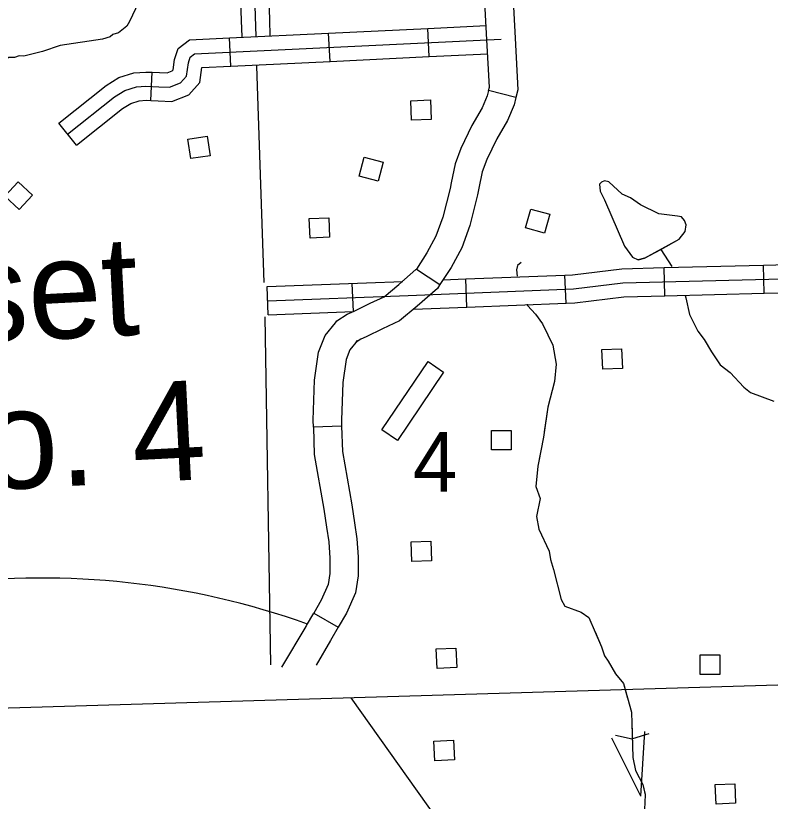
# Model space of a CAD drawing. Extents: x 1671357 to 13005564, y 567358 to 14261451.
# Drawn here: x 12758301.586 to 12758302.925, y 14259944.134 to 14259945.527 of the extents above; entities that cross this region are included whole.
import ezdxf

# ---------------------------------------------------------------- set-up
doc = ezdxf.new("R2010")
doc.units = 0
for name, color, linetype in [('31', 7, 'Continuous'), ('32', 7, 'Continuous'), ('35', 7, 'Continuous'), ('5', 7, 'Continuous'), ('56', 7, 'Continuous'), ('63', 7, 'Continuous'), ('Default', 7, 'Continuous')]:
    doc.layers.add(name, color=color, linetype=linetype)

msp = doc.modelspace()

# ---------------------------------------------------------------- linework, layer by layer
at = {"layer": '31'}
for p, q in [((12758302.4737, 14259945.3818), (12758302.4252, 14259945.3944)), ((12758302.2971, 14259945.0776), (12758302.3389, 14259945.0502)), ((12758302.1645, 14259944.7991), (12758302.1145, 14259944.7975)), ((12758302.1151, 14259944.4675), (12758302.1585, 14259944.4425)), ((12758302.1585, 14259944.4425), (12758302.1585, 14259944.4425))]:
    msp.add_line(p, q, dxfattribs=at)
for points in [[(12758301.9805, 14259945.6949), (12758301.9864, 14259945.5187)], [(12758302.0305, 14259945.6966), (12758302.0364, 14259945.5204)], [(12758302.4252, 14259945.3944), (12758302.4268, 14259945.4005), (12758302.4223, 14259945.4843), (12758302.4181, 14259945.5625)], [(12758302.4681, 14259945.5651), (12758302.4723, 14259945.487), (12758302.4772, 14259945.3955), (12758302.4737, 14259945.3818)], [(12758302.0364, 14259945.5204), (12758302.0374, 14259945.491)], [(12758301.9864, 14259945.5187), (12758301.9874, 14259945.4893)], [(12758302.4252, 14259945.3944), (12758302.4228, 14259945.385), (12758302.4138, 14259945.3636), (12758302.3955, 14259945.3322), (12758302.3758, 14259945.2916), (12758302.3657, 14259945.2641), (12758302.359, 14259945.2308)], [(12758302.4737, 14259945.3818), (12758302.4704, 14259945.369), (12758302.4587, 14259945.3412), (12758302.4397, 14259945.3087), (12758302.422, 14259945.272), (12758302.4141, 14259945.2504), (12758302.4081, 14259945.2209)], [(12758302.359, 14259945.2308), (12758302.3569, 14259945.2206), (12758302.3439, 14259945.1698), (12758302.3318, 14259945.1359), (12758302.3159, 14259945.1063), (12758302.2971, 14259945.0776)], [(12758302.4081, 14259945.2209), (12758302.4058, 14259945.2094), (12758302.3919, 14259945.1552), (12758302.3777, 14259945.1155), (12758302.359, 14259945.0807), (12758302.3389, 14259945.0502)], [(12758302.1535, 14259944.9824), (12758302.1562, 14259944.9857), (12758302.1745, 14259944.9975), (12758302.1867, 14259945.0029), (12758302.2153, 14259945.0172), (12758302.2401, 14259945.0285), (12758302.2661, 14259945.0502), (12758302.2964, 14259945.0767), (12758302.2971, 14259945.0776)], [(12758302.3389, 14259945.0502), (12758302.3345, 14259945.0434), (12758302.2986, 14259945.0121), (12758302.2671, 14259944.9858), (12758302.2369, 14259944.972), (12758302.208, 14259944.9576), (12758302.1985, 14259944.9534), (12758302.1902, 14259944.948), (12758302.1926, 14259944.951)], [(12758302.1145, 14259944.7975), (12758302.1141, 14259944.8099), (12758302.1166, 14259944.8809), (12758302.1236, 14259944.9304), (12758302.1355, 14259944.9598), (12758302.1535, 14259944.9824)], [(12758302.1926, 14259944.951), (12758302.1792, 14259944.9343), (12758302.1723, 14259944.9173), (12758302.1665, 14259944.8765), (12758302.1642, 14259944.8098), (12758302.1645, 14259944.7991)], [(12758302.1145, 14259944.7975), (12758302.116, 14259944.7487), (12758302.133, 14259944.6518), (12758302.1377, 14259944.6201)], [(12758302.1645, 14259944.7991), (12758302.1659, 14259944.7539), (12758302.1824, 14259944.6598), (12758302.1873, 14259944.6275)], [(12758302.1873, 14259944.6275), (12758302.1915, 14259944.5993), (12758302.1939, 14259944.5671), (12758302.1939, 14259944.5336), (12758302.1891, 14259944.5038), (12758302.1729, 14259944.4675), (12758302.1585, 14259944.4425)], [(12758302.1377, 14259944.6201), (12758302.1417, 14259944.5937), (12758302.1438, 14259944.5652), (12758302.1438, 14259944.5377), (12758302.1407, 14259944.5182), (12758302.1282, 14259944.4903), (12758302.1151, 14259944.4675)], [(12758302.1023, 14259944.4453), (12758302.1151, 14259944.4675)], [(12758302.0587, 14259944.3715), (12758302.1016, 14259944.4441), (12758302.1023, 14259944.4453)], [(12758302.1585, 14259944.4425), (12758302.1448, 14259944.4188), (12758302.1191, 14259944.3752)]]:
    msp.add_lwpolyline(points, dxfattribs=at)
at = {"layer": '32'}
for p, q in [((12758302.1439, 14259945.4461), (12758302.1415, 14259945.4961)), ((12758302.32, 14259945.4545), (12758302.3176, 14259945.5045)), ((12758301.9678, 14259945.4377), (12758301.9654, 14259945.4877)), ((12758301.826, 14259945.3766), (12758301.8283, 14259945.4267)), ((12758301.694, 14259945.2972), (12758301.6628, 14259945.3363)), ((12758302.7379, 14259945.0303), (12758302.7367, 14259945.0803)), ((12758302.9141, 14259945.0347), (12758302.9129, 14259945.0847)), ((12758302.3865, 14259945.0102), (12758302.3846, 14259945.0602)), ((12758302.5627, 14259945.0171), (12758302.5607, 14259945.0671)), ((12758302.0342, 14259944.9965), (12758302.0323, 14259945.0465)), ((12758302.1854, 14259945.0023), (12758302.1834, 14259945.0524))]:
    msp.add_line(p, q, dxfattribs=at)
for points in [[(12758302.3176, 14259945.5045), (12758302.4209, 14259945.5094)], [(12758301.9654, 14259945.4877), (12758302.1415, 14259945.4961)], [(12758302.1415, 14259945.4961), (12758302.3176, 14259945.5045)], [(12758301.6784, 14259945.3167), (12758301.7614, 14259945.3829), (12758301.7799, 14259945.3945), (12758301.8004, 14259945.401), (12758301.8174, 14259945.4021), (12758301.8404, 14259945.4011), (12758301.8592, 14259945.4002), (12758301.8785, 14259945.4081), (12758301.8891, 14259945.4196), (12758301.8927, 14259945.4435), (12758301.896, 14259945.4537), (12758301.9037, 14259945.4597), (12758302.4473, 14259945.4856)], [(12758301.8283, 14259945.4267), (12758301.8416, 14259945.4261), (12758301.8549, 14259945.4255), (12758301.8639, 14259945.4291), (12758301.8655, 14259945.4309), (12758301.8683, 14259945.4492), (12758301.8745, 14259945.4687), (12758301.8946, 14259945.4844), (12758301.9654, 14259945.4877)], [(12758302.1439, 14259945.4461), (12758302.32, 14259945.4545)], [(12758302.32, 14259945.4545), (12758302.4236, 14259945.4594)], [(12758301.826, 14259945.3766), (12758301.8393, 14259945.3761), (12758301.8635, 14259945.3749), (12758301.8932, 14259945.387), (12758301.9127, 14259945.4083), (12758301.9168, 14259945.4353), (12758301.9678, 14259945.4377)], [(12758301.9678, 14259945.4377), (12758302.1439, 14259945.4461)], [(12758301.6628, 14259945.3363), (12758301.7469, 14259945.4034), (12758301.7694, 14259945.4174), (12758301.7957, 14259945.4258), (12758301.8171, 14259945.4272), (12758301.8283, 14259945.4267)], [(12758301.694, 14259945.2972), (12758301.7759, 14259945.3625), (12758301.7905, 14259945.3716), (12758301.8051, 14259945.3762), (12758301.8176, 14259945.377), (12758301.826, 14259945.3766)], [(12758302.9129, 14259945.0847), (12758303.0891, 14259945.0891)], [(12758302.0333, 14259945.0215), (12758302.2823, 14259945.0311), (12758302.576, 14259945.0427), (12758302.6634, 14259945.0534), (12758303.3459, 14259945.0705), (12758303.4823, 14259945.076)], [(12758302.5607, 14259945.0671), (12758302.574, 14259945.0677), (12758302.6616, 14259945.0784), (12758302.7367, 14259945.0803)], [(12758302.7367, 14259945.0803), (12758302.9129, 14259945.0847)], [(12758302.3441, 14259945.0586), (12758302.3846, 14259945.0602)], [(12758302.3846, 14259945.0602), (12758302.5607, 14259945.0671)], [(12758302.0323, 14259945.0465), (12758302.2084, 14259945.0533)], [(12758302.2084, 14259945.0533), (12758302.2733, 14259945.0559)], [(12758302.7379, 14259945.0303), (12758302.9141, 14259945.0347)], [(12758302.9141, 14259945.0347), (12758303.0904, 14259945.0391)], [(12758302.5627, 14259945.0171), (12758302.5781, 14259945.0177), (12758302.6653, 14259945.0284), (12758302.7379, 14259945.0303)], [(12758302.2921, 14259945.0065), (12758302.3865, 14259945.0102)], [(12758302.3865, 14259945.0102), (12758302.5627, 14259945.0171)], [(12758302.0342, 14259944.9965), (12758302.1857, 14259945.0024)]]:
    msp.add_lwpolyline(points, dxfattribs=at)
at = {"layer": '35'}
for p, q in [((12758302.6502, 14259944.2513), (12758302.6799, 14259944.2444)), ((12758302.7095, 14259944.2534), (12758302.6803, 14259944.2445)), ((12758302.695, 14259944.1431), (12758302.7023, 14259944.2574)), ((12758302.695, 14259944.1431), (12758302.6441, 14259944.2457))]:
    msp.add_line(p, q, dxfattribs=at)
for points in [[(12758301.982, 14259945.6645), (12758301.9654, 14259945.6434), (12758301.9512, 14259945.624), (12758301.9323, 14259945.6044), (12758301.9217, 14259945.6026), (12758301.9082, 14259945.5983), (12758301.8803, 14259945.5938), (12758301.8453, 14259945.5923), (12758301.8292, 14259945.5869), (12758301.822, 14259945.5823), (12758301.8144, 14259945.5726), (12758301.7884, 14259945.5168), (12758301.7834, 14259945.5086), (12758301.7689, 14259945.4966), (12758301.7587, 14259945.4938), (12758301.7539, 14259945.4895), (12758301.7403, 14259945.4856), (12758301.6653, 14259945.4744), (12758301.6337, 14259945.4636), (12758301.6007, 14259945.4555), (12758301.5923, 14259945.4558), (12758301.5841, 14259945.4528), (12758301.5741, 14259945.4527), (12758301.5633, 14259945.4462)], [(12758302.731, 14259945.1123), (12758302.7633, 14259945.1308), (12758302.7737, 14259945.1443), (12758302.7759, 14259945.1564), (12758302.7729, 14259945.164), (12758302.7676, 14259945.1702), (12758302.7606, 14259945.1715), (12758302.727, 14259945.1758), (12758302.6949, 14259945.1915), (12758302.6767, 14259945.2042), (12758302.6624, 14259945.2106), (12758302.6388, 14259945.2324), (12758302.631, 14259945.2344), (12758302.6254, 14259945.2318), (12758302.6219, 14259945.2283), (12758302.6234, 14259945.2156), (12758302.6308, 14259945.2005)], [(12758302.6308, 14259945.2005), (12758302.6666, 14259945.1186), (12758302.6805, 14259945.0991), (12758302.6907, 14259945.0942), (12758302.7016, 14259945.097), (12758302.731, 14259945.1123)], [(12758302.7016, 14259945.097), (12758302.7633, 14259945.1308), (12758302.7737, 14259945.1443)], [(12758302.731, 14259945.1123), (12758302.7505, 14259945.0822)], [(12758302.4832, 14259945.0893), (12758302.4764, 14259945.084), (12758302.4748, 14259945.0762), (12758302.4759, 14259945.065)], [(12758302.7016, 14259945.097), (12758302.6907, 14259945.0942)], [(12758302.7738, 14259945.0307), (12758302.7751, 14259945.0267), (12758302.7817, 14259944.9972), (12758302.7963, 14259944.9673), (12758302.8076, 14259944.953), (12758302.8206, 14259944.9308), (12758302.8359, 14259944.908), (12758302.8539, 14259944.894), (12758302.8783, 14259944.8682), (12758302.8898, 14259944.859), (12758302.9315, 14259944.8437)], [(12758302.4934, 14259945.0153), (12758302.4945, 14259945.0131), (12758302.5085, 14259944.9976), (12758302.5209, 14259944.9803), (12758302.5392, 14259944.9426), (12758302.545, 14259944.909), (12758302.5423, 14259944.8783), (12758302.5305, 14259944.8326), (12758302.5224, 14259944.7796), (12758302.5126, 14259944.7279), (12758302.5092, 14259944.6919), (12758302.5167, 14259944.6708), (12758302.5101, 14259944.639), (12758302.5144, 14259944.6164), (12758302.5324, 14259944.5773), (12758302.535, 14259944.5627), (12758302.5405, 14259944.5448), (12758302.5537, 14259944.4917), (12758302.5606, 14259944.48), (12758302.5894, 14259944.4695), (12758302.6029, 14259944.46), (12758302.6254, 14259944.408), (12758302.6308, 14259944.3915), (12758302.6372, 14259944.3823), (12758302.6505, 14259944.3598), (12758302.6646, 14259944.343), (12758302.6785, 14259944.2919), (12758302.6812, 14259944.2116), (12758302.6859, 14259944.1884), (12758302.699, 14259944.1638)], [(12758302.4934, 14259945.0153), (12758302.4945, 14259945.0131), (12758302.5085, 14259944.9976), (12758302.5209, 14259944.9803), (12758302.5303, 14259944.961)], [(12758302.5432, 14259944.9193), (12758302.545, 14259944.909), (12758302.5423, 14259944.8783), (12758302.5305, 14259944.8326), (12758302.5239, 14259944.7893)], [(12758302.5161, 14259944.746), (12758302.5126, 14259944.7279), (12758302.5092, 14259944.6919), (12758302.5167, 14259944.6708), (12758302.5101, 14259944.639), (12758302.5143, 14259944.6167)], [(12758302.5325, 14259944.5766), (12758302.535, 14259944.5627), (12758302.5405, 14259944.5448), (12758302.5537, 14259944.4917), (12758302.5606, 14259944.48), (12758302.5894, 14259944.4695), (12758302.5897, 14259944.4692)], [(12758302.614, 14259944.4343), (12758302.6254, 14259944.408), (12758302.6308, 14259944.3915), (12758302.6372, 14259944.3823), (12758302.6505, 14259944.3598), (12758302.6646, 14259944.343), (12758302.6717, 14259944.317)], [(12758302.6791, 14259944.2739), (12758302.6812, 14259944.2116), (12758302.6859, 14259944.1884), (12758302.699, 14259944.1638), (12758302.7027, 14259944.1458)], [(12758302.699, 14259944.1638), (12758302.7027, 14259944.1455), (12758302.7015, 14259944.1193), (12758302.7032, 14259944.1103), (12758302.7169, 14259944.0878), (12758302.7357, 14259944.0692), (12758302.7453, 14259944.0471), (12758302.7536, 14259944.0106), (12758302.7532, 14259943.9791), (12758302.7386, 14259943.8836), (12758302.7356, 14259943.8436), (12758302.7394, 14259943.7546), (12758302.7436, 14259943.7437), (12758302.7687, 14259943.7183), (12758302.7759, 14259943.7069), (12758302.8193, 14259943.6591), (12758302.8255, 14259943.654), (12758302.8612, 14259943.6308), (12758302.8862, 14259943.6087), (12758302.899, 14259943.5902), (12758302.9033, 14259943.58)]]:
    msp.add_lwpolyline(points, dxfattribs=at)
at = {"layer": '5'}
for points in [[(12758301.9937, 14259946.0481), (12758302.0124, 14259945.4902)], [(12758302.0159, 14259945.3841), (12758302.0141, 14259945.438)], [(12758302.027, 14259945.0537), (12758302.0159, 14259945.3841)], [(12758302.0388, 14259944.3756), (12758302.0286, 14259944.9928)]]:
    msp.add_lwpolyline(points, dxfattribs=at)
at = {"layer": '56'}
for points in [[(12758302.2886, 14259945.3415), (12758302.2871, 14259945.3762), (12758302.322, 14259945.3777), (12758302.3234, 14259945.343)], [(12758301.8917, 14259945.3083), (12758301.9261, 14259945.3133), (12758301.9311, 14259945.2788), (12758301.8967, 14259945.2738)], [(12758302.1958, 14259945.2426), (12758302.2047, 14259945.2762), (12758302.2384, 14259945.2673), (12758302.2295, 14259945.2337)], [(12758301.567, 14259945.2069), (12758301.5906, 14259945.2324), (12758301.6162, 14259945.2087), (12758301.5926, 14259945.1832)], [(12758302.4908, 14259945.1507), (12758302.5001, 14259945.1842), (12758302.5337, 14259945.1749), (12758302.5244, 14259945.1414)], [(12758302.1084, 14259945.1326), (12758302.1069, 14259945.1673), (12758302.1417, 14259945.1688), (12758302.1432, 14259945.1341)], [(12758302.6278, 14259944.9001), (12758302.6263, 14259944.9348), (12758302.6611, 14259944.9363), (12758302.6626, 14259944.9015)], [(12758302.3178, 14259944.9135), (12758302.3455, 14259944.8948), (12758302.2635, 14259944.7739), (12758302.2358, 14259944.7927)], [(12758302.4302, 14259944.7569), (12758302.4302, 14259944.7917), (12758302.4651, 14259944.7917), (12758302.4651, 14259944.7569)], [(12758302.2892, 14259944.559), (12758302.2878, 14259944.5937), (12758302.3226, 14259944.5952), (12758302.3241, 14259944.5604)], [(12758302.3339, 14259944.3694), (12758302.3324, 14259944.4041), (12758302.3672, 14259944.4056), (12758302.3687, 14259944.3709)], [(12758302.8004, 14259944.3587), (12758302.8004, 14259944.3934), (12758302.8352, 14259944.3934), (12758302.8352, 14259944.3587)], [(12758302.3297, 14259944.2058), (12758302.3283, 14259944.2405), (12758302.3631, 14259944.242), (12758302.3646, 14259944.2073)], [(12758302.8287, 14259944.1287), (12758302.8272, 14259944.1634), (12758302.862, 14259944.1649), (12758302.8635, 14259944.1302)]]:
    msp.add_lwpolyline(points, close=True, dxfattribs=at)
at = {"layer": '63'}
msp.add_arc((12758301.6325, 14259943.1312), 1.3986, 70.3026, 123.572, dxfattribs=at)
at = {"layer": 'Default'}
msp.add_line((12758310.0419, 14259944.551), (12758300.287, 14259944.2608), dxfattribs=at)
msp.add_lwpolyline([(12758300.287, 14259944.2608), (12758302.6359, 14259943.6777), (12758302.1816, 14259944.3171)], dxfattribs=at)

# ---------------------------------------------------------------- texts
at = {"layer": '56'}
msp.add_text('4', height=0.1058, dxfattribs=at).set_placement((12758302.2908, 14259944.683))
at = {"layer": '63'}
for s, p in [('Inset', (12758301.2976, 14259944.9358)), ('No. 4', (12758301.3642, 14259944.6769))]:
    msp.add_text(s, height=0.17628, rotation=2.8934, dxfattribs=at).set_placement(p)

doc.saveas('drawing.dxf')
